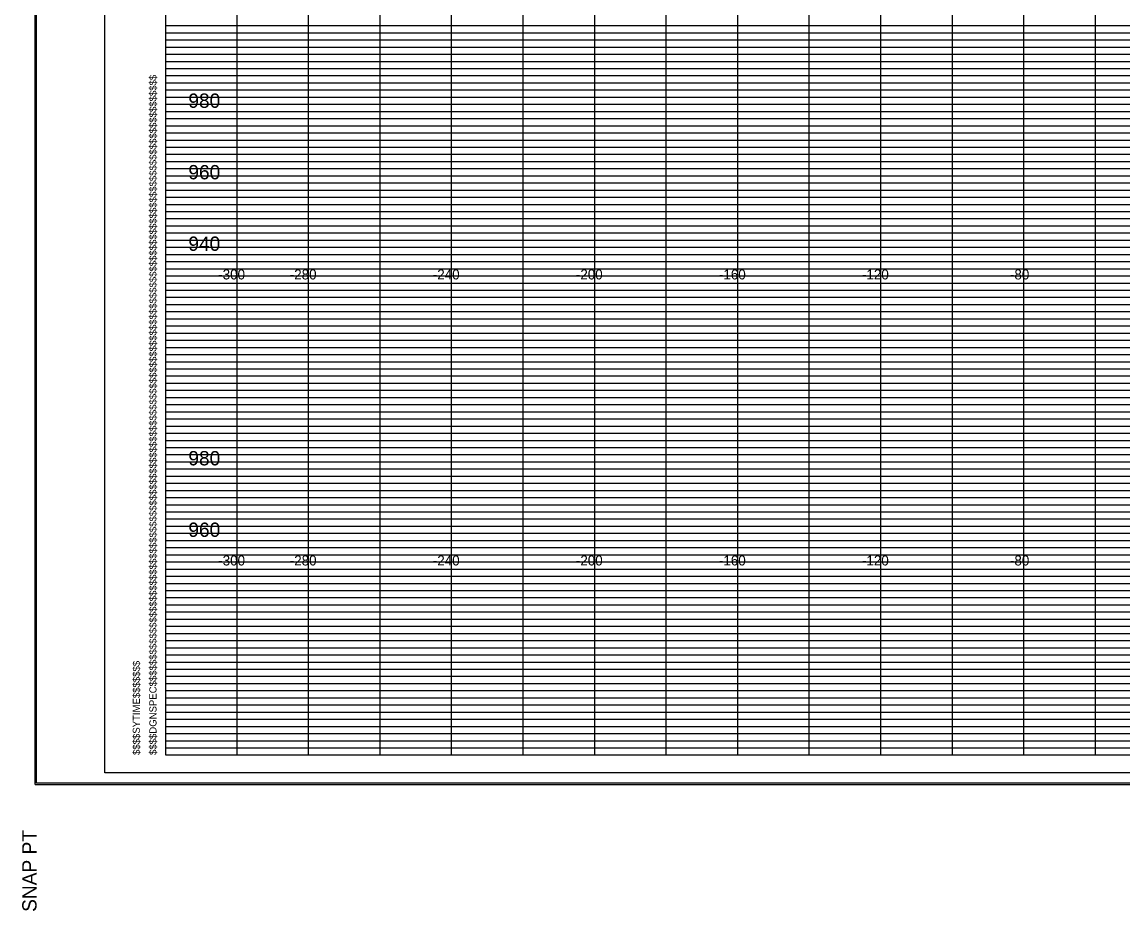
# Model space of a CAD drawing. Extents: x 2313580 to 2322968, y 282099 to 303247.
# Drawn here: x 2318423.6 to 2318731.4, y 287544 to 287792.7 of the extents above; entities that cross this region are included whole.
import ezdxf

# ---------------------------------------------------------------- set-up
doc = ezdxf.new("R2010")
doc.units = 0
for name, color, linetype in [('DESIGN - SHEET - Corner Text', 7, 'Continuous'), ('DESIGN - SHEET - Light Grid', 7, 'Continuous'), ('DESIGN - SHEET - Linework', 7, 'Continuous'), ('DESIGN - SHEET - Plot Shape', 7, 'Continuous'), ('DESIGN - TYPICAL - Text', 7, 'Continuous')]:
    doc.layers.add(name, color=color, linetype=linetype)

msp = doc.modelspace()

# ---------------------------------------------------------------- linework, layer by layer
at = {"layer": 'DESIGN - SHEET - Light Grid'}
for p, q in [((2318463.68, 287791.67), (2318623.68, 287791.67)), ((2318623.68, 287791.67), (2318783.68, 287791.67)), ((2318463.68, 287789.67), (2318623.68, 287789.67)), ((2318623.68, 287789.67), (2318783.68, 287789.67)), ((2318463.68, 287785.67), (2318623.68, 287785.67)), ((2318623.68, 287785.67), (2318783.68, 287785.67)), ((2318463.68, 287783.67), (2318623.68, 287783.67)), ((2318623.68, 287783.67), (2318783.68, 287783.67)), ((2318463.68, 287781.67), (2318623.68, 287781.67)), ((2318463.68, 287779.67), (2318623.68, 287779.67)), ((2318623.68, 287781.67), (2318783.68, 287781.67)), ((2318623.68, 287779.67), (2318783.68, 287779.67)), ((2318463.68, 287777.67), (2318623.68, 287777.67)), ((2318623.68, 287777.67), (2318783.68, 287777.67)), ((2318463.68, 287775.67), (2318623.68, 287775.67)), ((2318463.68, 287773.67), (2318623.68, 287773.67)), ((2318623.68, 287775.67), (2318783.68, 287775.67)), ((2318623.68, 287773.67), (2318783.68, 287773.67)), ((2318463.68, 287771.67), (2318623.68, 287771.67)), ((2318623.68, 287771.67), (2318783.68, 287771.67)), ((2318463.68, 287769.67), (2318623.68, 287769.67)), ((2318623.68, 287769.67), (2318783.68, 287769.67)), ((2318463.68, 287765.67), (2318623.68, 287765.67)), ((2318463.68, 287763.67), (2318623.68, 287763.67)), ((2318623.68, 287765.67), (2318783.68, 287765.67)), ((2318623.68, 287763.67), (2318783.68, 287763.67)), ((2318463.68, 287761.67), (2318623.68, 287761.67)), ((2318623.68, 287761.67), (2318783.68, 287761.67)), ((2318463.68, 287759.67), (2318623.68, 287759.67)), ((2318463.68, 287757.67), (2318623.68, 287757.67)), ((2318623.68, 287759.67), (2318783.68, 287759.67)), ((2318623.68, 287757.67), (2318783.68, 287757.67)), ((2318463.68, 287755.67), (2318623.68, 287755.67)), ((2318623.68, 287755.67), (2318783.68, 287755.67)), ((2318463.68, 287753.67), (2318623.68, 287753.67)), ((2318463.68, 287751.67), (2318623.68, 287751.67)), ((2318623.68, 287753.67), (2318783.68, 287753.67)), ((2318623.68, 287751.67), (2318783.68, 287751.67)), ((2318463.68, 287749.67), (2318623.68, 287749.67)), ((2318623.68, 287749.67), (2318783.68, 287749.67)), ((2318463.68, 287745.67), (2318623.68, 287745.67)), ((2318623.68, 287745.67), (2318783.68, 287745.67)), ((2318463.68, 287743.67), (2318623.68, 287743.67)), ((2318623.68, 287743.67), (2318783.68, 287743.67)), ((2318463.68, 287741.67), (2318623.68, 287741.67)), ((2318463.68, 287739.67), (2318623.68, 287739.67)), ((2318623.68, 287741.67), (2318783.68, 287741.67)), ((2318623.68, 287739.67), (2318783.68, 287739.67)), ((2318463.68, 287737.67), (2318623.68, 287737.67)), ((2318623.68, 287737.67), (2318783.68, 287737.67)), ((2318463.68, 287735.67), (2318623.68, 287735.67)), ((2318463.68, 287733.67), (2318623.68, 287733.67)), ((2318623.68, 287735.67), (2318783.68, 287735.67)), ((2318623.68, 287733.67), (2318783.68, 287733.67)), ((2318463.68, 287731.67), (2318623.68, 287731.67)), ((2318623.68, 287731.67), (2318783.68, 287731.67)), ((2318463.68, 287729.67), (2318623.68, 287729.67)), ((2318623.68, 287729.67), (2318783.68, 287729.67)), ((2318463.68, 287725.67), (2318623.68, 287725.67)), ((2318463.68, 287723.67), (2318623.68, 287723.67)), ((2318623.68, 287725.67), (2318783.68, 287725.67)), ((2318623.68, 287723.67), (2318783.68, 287723.67)), ((2318463.68, 287721.67), (2318623.68, 287721.67)), ((2318623.68, 287721.67), (2318783.68, 287721.67)), ((2318463.68, 287719.67), (2318623.68, 287719.67)), ((2318463.68, 287717.67), (2318623.68, 287717.67)), ((2318623.68, 287719.67), (2318783.68, 287719.67)), ((2318623.68, 287717.67), (2318783.68, 287717.67)), ((2318463.68, 287715.67), (2318623.68, 287715.67)), ((2318623.68, 287715.67), (2318783.68, 287715.67)), ((2318463.68, 287713.67), (2318623.68, 287713.67)), ((2318463.68, 287711.67), (2318623.68, 287711.67)), ((2318623.68, 287713.67), (2318783.68, 287713.67)), ((2318623.68, 287711.67), (2318783.68, 287711.67)), ((2318463.68, 287709.67), (2318623.68, 287709.67)), ((2318623.68, 287709.67), (2318783.68, 287709.67)), ((2318463.68, 287705.67), (2318623.68, 287705.67)), ((2318623.68, 287705.67), (2318783.68, 287705.67)), ((2318463.68, 287703.67), (2318623.68, 287703.67)), ((2318623.68, 287703.67), (2318783.68, 287703.67)), ((2318463.68, 287701.67), (2318623.68, 287701.67)), ((2318463.68, 287699.67), (2318623.68, 287699.67)), ((2318623.68, 287701.67), (2318783.68, 287701.67)), ((2318623.68, 287699.67), (2318783.68, 287699.67)), ((2318463.68, 287697.67), (2318623.68, 287697.67)), ((2318623.68, 287697.67), (2318783.68, 287697.67)), ((2318463.68, 287695.67), (2318623.68, 287695.67)), ((2318463.68, 287693.67), (2318623.68, 287693.67)), ((2318623.68, 287695.67), (2318783.68, 287695.67)), ((2318623.68, 287693.67), (2318783.68, 287693.67)), ((2318463.68, 287691.67), (2318623.68, 287691.67)), ((2318623.68, 287691.67), (2318783.68, 287691.67)), ((2318463.68, 287689.67), (2318623.68, 287689.67)), ((2318623.68, 287689.67), (2318783.68, 287689.67)), ((2318463.68, 287685.67), (2318623.68, 287685.67)), ((2318463.68, 287683.67), (2318623.68, 287683.67)), ((2318623.68, 287685.67), (2318783.68, 287685.67)), ((2318623.68, 287683.67), (2318783.68, 287683.67)), ((2318463.68, 287681.67), (2318623.68, 287681.67)), ((2318623.68, 287681.67), (2318783.68, 287681.67)), ((2318463.68, 287679.67), (2318623.68, 287679.67)), ((2318463.68, 287677.67), (2318623.68, 287677.67)), ((2318623.68, 287679.67), (2318783.68, 287679.67)), ((2318623.68, 287677.67), (2318783.68, 287677.67)), ((2318463.68, 287675.67), (2318623.68, 287675.67)), ((2318623.68, 287675.67), (2318783.68, 287675.67)), ((2318463.68, 287673.67), (2318623.68, 287673.67)), ((2318463.68, 287671.67), (2318623.68, 287671.67)), ((2318623.68, 287673.67), (2318783.68, 287673.67)), ((2318623.68, 287671.67), (2318783.68, 287671.67)), ((2318463.68, 287669.67), (2318623.68, 287669.67)), ((2318623.68, 287669.67), (2318783.68, 287669.67)), ((2318463.68, 287665.67), (2318623.68, 287665.67)), ((2318623.68, 287665.67), (2318783.68, 287665.67)), ((2318463.68, 287663.67), (2318623.68, 287663.67)), ((2318623.68, 287663.67), (2318783.68, 287663.67)), ((2318463.68, 287661.67), (2318623.68, 287661.67)), ((2318463.68, 287659.67), (2318623.68, 287659.67)), ((2318623.68, 287661.67), (2318783.68, 287661.67)), ((2318623.68, 287659.67), (2318783.68, 287659.67)), ((2318463.68, 287657.67), (2318623.68, 287657.67)), ((2318623.68, 287657.67), (2318783.68, 287657.67)), ((2318463.68, 287655.67), (2318623.68, 287655.67)), ((2318463.68, 287653.67), (2318623.68, 287653.67)), ((2318623.68, 287655.67), (2318783.68, 287655.67)), ((2318623.68, 287653.67), (2318783.68, 287653.67)), ((2318463.68, 287651.67), (2318623.68, 287651.67)), ((2318623.68, 287651.67), (2318783.68, 287651.67)), ((2318463.68, 287649.67), (2318623.68, 287649.67)), ((2318623.68, 287649.67), (2318783.68, 287649.67)), ((2318463.68, 287645.67), (2318623.68, 287645.67)), ((2318463.68, 287643.67), (2318623.68, 287643.67)), ((2318623.68, 287645.67), (2318783.68, 287645.67)), ((2318623.68, 287643.67), (2318783.68, 287643.67)), ((2318463.68, 287641.67), (2318623.68, 287641.67)), ((2318623.68, 287641.67), (2318783.68, 287641.67)), ((2318463.68, 287639.67), (2318623.68, 287639.67)), ((2318463.68, 287637.67), (2318623.68, 287637.67)), ((2318623.68, 287639.67), (2318783.68, 287639.67)), ((2318623.68, 287637.67), (2318783.68, 287637.67)), ((2318463.68, 287635.67), (2318623.68, 287635.67)), ((2318623.68, 287635.67), (2318783.68, 287635.67)), ((2318463.68, 287633.67), (2318623.68, 287633.67)), ((2318463.68, 287631.67), (2318623.68, 287631.67)), ((2318623.68, 287633.67), (2318783.68, 287633.67)), ((2318623.68, 287631.67), (2318783.68, 287631.67)), ((2318463.68, 287629.67), (2318623.68, 287629.67)), ((2318623.68, 287629.67), (2318783.68, 287629.67)), ((2318463.68, 287625.67), (2318623.68, 287625.67)), ((2318623.68, 287625.67), (2318783.68, 287625.67)), ((2318463.68, 287623.67), (2318623.68, 287623.67)), ((2318623.68, 287623.67), (2318783.68, 287623.67)), ((2318463.68, 287621.67), (2318623.68, 287621.67)), ((2318463.68, 287619.67), (2318623.68, 287619.67)), ((2318623.68, 287621.67), (2318783.68, 287621.67)), ((2318623.68, 287619.67), (2318783.68, 287619.67)), ((2318463.68, 287617.67), (2318623.68, 287617.67)), ((2318623.68, 287617.67), (2318783.68, 287617.67)), ((2318463.68, 287615.67), (2318623.68, 287615.67)), ((2318463.68, 287613.67), (2318623.68, 287613.67)), ((2318623.68, 287615.67), (2318783.68, 287615.67)), ((2318623.68, 287613.67), (2318783.68, 287613.67)), ((2318463.68, 287611.67), (2318623.68, 287611.67)), ((2318463.68, 287609.67), (2318623.68, 287609.67)), ((2318623.68, 287611.67), (2318783.68, 287611.67)), ((2318623.68, 287609.67), (2318783.68, 287609.67)), ((2318463.68, 287605.67), (2318623.68, 287605.67)), ((2318463.68, 287603.67), (2318623.68, 287603.67)), ((2318623.68, 287605.67), (2318783.68, 287605.67)), ((2318623.68, 287603.67), (2318783.68, 287603.67)), ((2318463.68, 287601.67), (2318623.68, 287601.67)), ((2318623.68, 287601.67), (2318783.68, 287601.67)), ((2318463.68, 287599.67), (2318623.68, 287599.67)), ((2318463.68, 287597.67), (2318623.68, 287597.67)), ((2318623.68, 287599.67), (2318783.68, 287599.67)), ((2318623.68, 287597.67), (2318783.68, 287597.67)), ((2318463.68, 287595.67), (2318623.68, 287595.67)), ((2318623.68, 287595.67), (2318783.68, 287595.67)), ((2318463.68, 287593.67), (2318623.68, 287593.67)), ((2318463.68, 287591.67), (2318623.68, 287591.67)), ((2318623.68, 287593.67), (2318783.68, 287593.67)), ((2318623.68, 287591.67), (2318783.68, 287591.67)), ((2318463.68, 287589.67), (2318623.68, 287589.67)), ((2318623.68, 287589.67), (2318783.68, 287589.67))]:
    msp.add_line(p, q, dxfattribs=at)
at = {"layer": 'DESIGN - SHEET - Linework'}
for p, q in [((2318427.22, 287579.39), (2318427.22, 288015.95)), ((2318483.68, 287587.67), (2318483.68, 288007.67)), ((2318503.68, 287587.67), (2318503.68, 288007.67)), ((2318523.68, 287587.67), (2318523.68, 288007.67)), ((2318543.68, 287587.67), (2318543.68, 288007.67)), ((2318563.68, 287587.67), (2318563.68, 288007.67)), ((2318583.68, 287587.67), (2318583.68, 288007.67)), ((2318603.68, 287587.67), (2318603.68, 288007.67)), ((2318623.68, 287587.67), (2318623.68, 288007.67)), ((2318643.68, 287587.67), (2318643.68, 288007.67)), ((2318663.68, 287587.67), (2318663.68, 288007.67)), ((2318683.68, 287587.67), (2318683.68, 288007.67)), ((2318703.68, 287587.67), (2318703.68, 288007.67)), ((2318723.68, 287587.67), (2318723.68, 288007.67)), ((2318463.68, 287787.67), (2319103.68, 287787.67)), ((2318463.68, 287767.67), (2319103.68, 287767.67)), ((2318463.68, 287747.67), (2319103.68, 287747.67)), ((2318463.68, 287727.67), (2319103.68, 287727.67)), ((2318463.68, 287707.67), (2319103.68, 287707.67)), ((2318463.68, 287687.67), (2319103.68, 287687.67)), ((2318463.68, 287667.67), (2319103.68, 287667.67)), ((2318463.68, 287647.67), (2319103.68, 287647.67)), ((2318463.68, 287627.67), (2319103.68, 287627.67)), ((2318463.68, 287607.67), (2319103.68, 287607.67)), ((2318427.22, 287579.39), (2319108.02, 287579.39))]:
    msp.add_line(p, q, dxfattribs=at)
msp.add_lwpolyline([(2318463.68, 288007.67), (2318463.68, 287587.67), (2319103.68, 287587.67), (2319103.68, 288007.67), (2318463.68, 288007.67)], dxfattribs=at)
at = {"layer": 'DESIGN - SHEET - Plot Shape'}
for points in [[(2318427.62, 288015.55), (2319107.62, 288015.55), (2319107.62, 287579.79), (2318427.62, 287579.79)], [(2318446.68, 288007.67), (2319103.68, 288007.67), (2319103.68, 287582.67), (2318446.68, 287582.67)]]:
    msp.add_lwpolyline(points, close=True, dxfattribs=at)

# ---------------------------------------------------------------- texts
at = {"layer": 'DESIGN - SHEET - Corner Text'}
for s, height, p in [('$$$$DGNSPEC$$$$$$$$$$$$$$$$$$$$$$$$$$$$$$$$$$$$$$$$$$$$$$$$$$$$$$$$$$$$$$$$$$$$$$$$$$$$$$$$$$$$$$$$$$$$$$$$$$$$$$$$$$$$$$$$$$$', 2.00004, (2318461.16, 287587.67)), ('$$$$SYTIME$$$$$$$', 2, (2318456.52, 287587.67)), ('SNAP PT  ', 4, (2318427.62, 287543.79))]:
    msp.add_text(s, height=height, rotation=90, dxfattribs=at).set_placement(p)
at = {"layer": 'DESIGN - SHEET - Linework'}
for p in [(2318483.68, 287727.67), (2318483.68, 287647.67)]:
    msp.add_text('-', height=0.0001, dxfattribs=at).set_placement(p)
at = {"layer": 'DESIGN - TYPICAL - Text'}
for s, height, p in [('980', 4, (2318470.06, 287768.67)), ('960', 4, (2318470.06, 287748.67)), ('940', 4, (2318470.06, 287728.67)), ('-300', 2.8, (2318478.42, 287720.67)), ('-280', 2.8, (2318498.42, 287720.67)), ('-240', 2.8, (2318538.42, 287720.67)), ('-200', 2.8, (2318578.42, 287720.67)), ('-160', 2.8, (2318618.42, 287720.67)), ('-120', 2.8, (2318658.42, 287720.67)), ('-80', 2.8, (2318699.79, 287720.67)), ('980', 4, (2318470.06, 287668.67)), ('960', 4, (2318470.06, 287648.67)), ('-300', 2.8, (2318478.42, 287640.67)), ('-280', 2.8, (2318498.42, 287640.67)), ('-240', 2.8, (2318538.42, 287640.67)), ('-200', 2.8, (2318578.42, 287640.67)), ('-160', 2.8, (2318618.42, 287640.67)), ('-120', 2.8, (2318658.42, 287640.67)), ('-80', 2.8, (2318699.79, 287640.67))]:
    msp.add_text(s, height=height, dxfattribs=at).set_placement(p)

doc.saveas('drawing.dxf')
